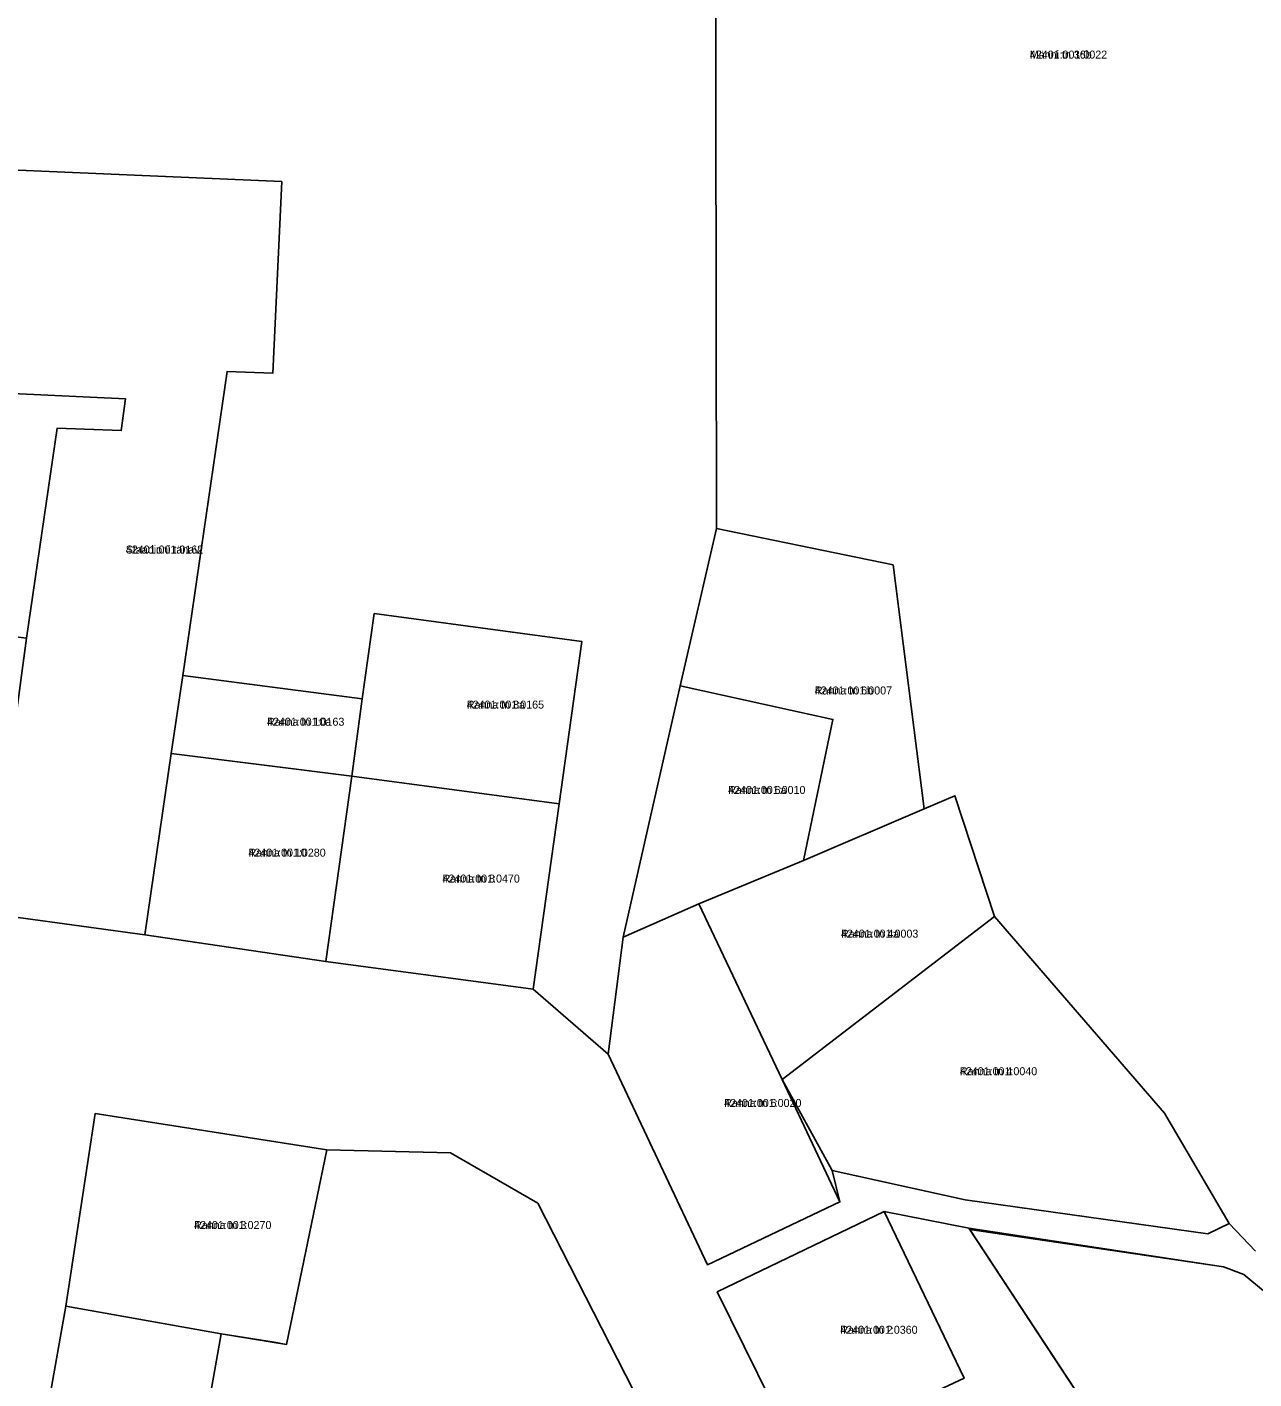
# Model space of a CAD drawing. Extents: x 595979 to 597983, y 6604231 to 6607350.
# Drawn here: x 597024.3 to 597254.4, y 6605469.2 to 6605722.5 of the extents above; entities that cross this region are included whole.
import ezdxf

# ---------------------------------------------------------------- set-up
doc = ezdxf.new("R2010")
doc.units = 0
for name, color, linetype in [('L_AADRESS', 7, 'Continuous'), ('PIIR', 7, 'Continuous'), ('TUNNUS', 7, 'Continuous')]:
    doc.layers.add(name, color=color, linetype=linetype)

msp = doc.modelspace()

# ---------------------------------------------------------------- linework, layer by layer
at = {"layer": 'PIIR'}
for points in [[(597254.66, 6605493.15), (597249.71, 6605498.34), (597237.59, 6605519.02), (597205.75, 6605555.84), (597198.31, 6605578.46), (597192.52, 6605576.03), (597186.73, 6605621.73), (597153.6, 6605628.55), (597153.23, 6605871.03), (597225.11, 6605957.9), (597234.32, 6605943.41), (597245.66, 6605929.36), (597258.88, 6605918.33)], [(597004.6, 6605901.84), (597028.34, 6605885.84), (597031.31, 6605885.03), (597042.72, 6605888.08), (597054.7, 6605908.63), (597056.42, 6605921), (597069.54, 6605924.99), (597061.14, 6605894.65), (597112.11, 6605879.53), (597153.23, 6605871.03), (597153.6, 6605628.55), (597146.78, 6605599.1), (597136.13, 6605552), (597133.33, 6605530.05), (597119.25, 6605542.22), (597124.12, 6605576.98), (597128.37, 6605607.35), (597089.46, 6605612.62), (597087.2, 6605596.63), (597053.54, 6605601.01), (597061.85, 6605657.99), (597070.41, 6605657.66), (597072.09, 6605693.55), (597015.38, 6605695.99)], [(597006.53, 6605453.26), (597011.61, 6605485.87), (597017.75, 6605525.39), (597014.88, 6605556.72), (597046.44, 6605552.43), (597080.35, 6605547.38), (597119.25, 6605542.22), (597133.33, 6605530.05), (597151.91, 6605490.59), (597176.76, 6605502.37), (597175.32, 6605508.24), (597200.25, 6605502.72), (597245.72, 6605496.35), (597249.71, 6605498.34), (597254.66, 6605493.15)], [(597138.08, 6605467.03), (597120.14, 6605502.12), (597103.73, 6605511.53), (597080.58, 6605512.09), (597037.11, 6605518.9), (597031.63, 6605482.83), (597024.43, 6605442.28)], [(597262.8, 6605480.17), (597252.5, 6605488.75), (597248.64, 6605490.2), (597200.9, 6605497.42), (597185.05, 6605500.54), (597153.75, 6605485.48), (597168.9, 6605454.75)]]:
    msp.add_lwpolyline(points, dxfattribs=at)
for points in [[(596996.56, 6605681.6), (597015.83, 6605704.95), (597015.38, 6605695.99), (597013.65, 6605654.21), (597042.81, 6605652.85), (597042.02, 6605646.89), (597030, 6605647.37), (597024.26, 6605607.99), (596988.68, 6605612.52), (596957.38, 6605616.65), (596954.75, 6605616.95), (596984.67, 6605663.14)], [(597013.65, 6605654.21), (597015.38, 6605695.99), (597072.09, 6605693.55), (597070.41, 6605657.66), (597061.85, 6605657.99), (597053.54, 6605601.01), (597051.38, 6605586.37), (597046.44, 6605552.43), (597014.88, 6605556.72), (597022.14, 6605592.15), (597024.26, 6605607.99), (597030, 6605647.37), (597042.02, 6605646.89), (597042.81, 6605652.85)], [(597153.6, 6605628.55), (597186.73, 6605621.73), (597192.52, 6605576.03), (597169.9, 6605566.35), (597175.45, 6605592.77), (597146.78, 6605599.1)], [(597087.2, 6605596.63), (597089.46, 6605612.62), (597128.37, 6605607.35), (597124.12, 6605576.98), (597085.25, 6605582.17)], [(597051.38, 6605586.37), (597053.54, 6605601.01), (597087.2, 6605596.63), (597085.25, 6605582.17)], [(597175.45, 6605592.77), (597169.9, 6605566.35), (597150.29, 6605558.23), (597136.13, 6605552), (597146.78, 6605599.1)], [(597051.38, 6605586.37), (597085.25, 6605582.17), (597080.35, 6605547.38), (597046.44, 6605552.43)], [(597085.25, 6605582.17), (597124.12, 6605576.98), (597119.25, 6605542.22), (597080.35, 6605547.38)], [(597169.9, 6605566.35), (597192.52, 6605576.03), (597198.31, 6605578.46), (597205.75, 6605555.84), (597165.95, 6605525.29), (597150.29, 6605558.23)], [(597176.76, 6605502.37), (597151.91, 6605490.59), (597133.33, 6605530.05), (597136.13, 6605552), (597150.29, 6605558.23), (597165.95, 6605525.29)], [(597175.32, 6605508.24), (597165.95, 6605525.29), (597205.75, 6605555.84), (597237.59, 6605519.02), (597249.71, 6605498.34), (597245.72, 6605496.35), (597200.25, 6605502.72), (597185.49, 6605506.02)], [(597037.11, 6605518.9), (597080.58, 6605512.09), (597073.01, 6605475.66), (597060.74, 6605477.66), (597031.63, 6605482.83)], [(597073.01, 6605475.66), (597080.58, 6605512.09), (597103.73, 6605511.53), (597120.14, 6605502.12), (597138.08, 6605467.03), (597100.31, 6605449.17), (597113.74, 6605424.04), (597007.88, 6605367.24), (597018.25, 6605402.38), (597047.55, 6605397.79), (597053.68, 6605437.8), (597060.74, 6605477.66), (597070.69, 6605476.05)], [(597185.05, 6605500.54), (597200.03, 6605469.31), (597168.9, 6605454.75), (597153.75, 6605485.48)], [(597185.05, 6605500.54), (597200.9, 6605497.42), (597231.46, 6605450.99), (597217.98, 6605443.18), (597227.8, 6605420.87), (597194, 6605402.66), (597168.9, 6605454.75), (597200.03, 6605469.31)], [(597232.23, 6605450.89), (597231.64, 6605450.82), (597201.09, 6605497.22), (597248.64, 6605490.2), (597252.5, 6605488.75), (597262.8, 6605480.17), (597301.12, 6605469.32), (597304.83, 6605462.35), (597246.04, 6605430.3)], [(597031.63, 6605482.83), (597060.74, 6605477.66), (597053.68, 6605437.79), (597024.43, 6605442.28)]]:
    msp.add_lwpolyline(points, close=True, dxfattribs=at)

# ---------------------------------------------------------------- texts
at = {"layer": 'L_AADRESS'}
for s, p in [('Männi tn 36b', (597212.36, 6605716.61)), ('Staadioni tänav', (597042.87, 6605623.86)), ('Ranna tn 6b', (597172.03, 6605597.45)), ('Ranna tn 8a', (597106.78, 6605594.8)), ('Ranna tn 10a', (597069.34, 6605591.59)), ('Ranna tn 6a', (597155.79, 6605578.81)), ('Ranna tn 10', (597065.84, 6605567.06)), ('Ranna tn 8', (597102.24, 6605562.2)), ('Ranna tn 4a', (597176.95, 6605551.88)), ('Ranna tn 4', (597199.24, 6605526.1)), ('Ranna tn 6', (597155.04, 6605520.15)), ('Ranna tn 3', (597055.66, 6605497.28)), ('Ranna tn 2', (597176.82, 6605477.65))]:
    msp.add_text(s, height=1.5, dxfattribs=at).set_placement(p)
at = {"layer": 'TUNNUS'}
for s, p in [('42401:001:0022', (597212.36, 6605716.61)), ('42401:001:0162', (597042.87, 6605623.86)), ('42401:001:0007', (597172.03, 6605597.45)), ('42401:001:0165', (597106.78, 6605594.8)), ('42401:001:0163', (597069.34, 6605591.59)), ('42401:001:0010', (597155.79, 6605578.81)), ('42401:001:0280', (597065.84, 6605567.06)), ('42401:001:0470', (597102.24, 6605562.2)), ('42401:001:0003', (597176.95, 6605551.88)), ('42401:001:0040', (597199.24, 6605526.1)), ('42401:001:0020', (597155.04, 6605520.15)), ('42401:001:0270', (597055.66, 6605497.28)), ('42401:001:0360', (597176.82, 6605477.65))]:
    msp.add_text(s, height=1.5, dxfattribs=at).set_placement(p)

doc.saveas('drawing.dxf')
